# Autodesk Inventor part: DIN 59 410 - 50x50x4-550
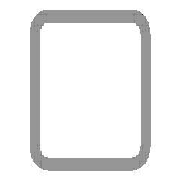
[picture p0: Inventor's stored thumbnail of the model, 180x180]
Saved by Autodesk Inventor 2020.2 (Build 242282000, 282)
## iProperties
Manager: www.cadconsulting.pl
Company: Fabian Stasiak CAD Consulting
Created: 2015-01
Part Number: DIN 59 410 - 50x50x4-550
Material: Stal, miękka
Description: Rurki stalowe o przekroju kwadratowym formowane na gorąco
Document SubType Name: Modellieren
Standard: DIN
Designer: F.Stasiak
Standards Organization: DIN
Language: pl-PL
Size Designation: 50x50x4
Categories: <MemberInstance><Categories><Category DisplayName="Kształtowniki konstrukcyjne" InternalName="089c4875-fa83-4c05-b084-43b9cc11f5ed" Mnemonic="GRDR"><CategoryPar
Stock Number: 50x50x4
Density: 7.85 g/cm^3
Appearance: Częściowo polerowana
Mass: 2999.78 g
Surface Area: 1924.59 cm^2
Volume: 382.138 cm^3
Catalog Web Link: www.expertbooks.pl
_CCFamilyMember: 40
_CCFamilyDisplayName: DIN 59410 (Kwadrat) - Rurki stalowe o przekroju kwadratowym formowane na gorąco
_FrameMemberDoc: Frame Member File
_Version: 15.0.0
_GetPNFromCC: 1
G_W: 50,000 mm
G_H: 50,000 mm
+8E38D49E-AF55-4C8E-92AA-B8B39F08F457+CUTDETAIL1: Wytnij
+63F55C9A-EFE3-425B-B887-7A3715F28EA0+CUTDETAIL2: Wytnij
G_L: 550,000 mm
IsCustomPart: 1
Author: F.Stasiak
Subject: Zbiór ćwiczeń. Autodesk Inventor 2020. Kurs Professional
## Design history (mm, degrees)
node "Płaszczyzna początkowa"
node "Płaszczyzna końcowa"
sketch "Szkic"
  geometry: L1 (-17, 25)-(17, 25); L2 (25, 17)-(25, -17); L3 (17, -25)-(-17, -25); L4 (-25, -17)-(-25, 17); L5 (-37.32, 0)-(37.32, 0) reference; L6 (0, -37.32)-(0, 37.32) reference; L7 (-17, 21)-(17, 21); L8 (21, 17)-(21, -17); L9 (17, -21)-(-17, -21); L10 (-21, -17)-(-21, 17); A1 r 8 centre (-17, 17) between (-17, 25) and (-25, 17); A2 r 8 centre (17, 17) between (25, 17) and (17, 25); A3 r 8 centre (17, -17) between (17, -25) and (25, -17); A4 r 8 centre (-17, -17) between (-25, -17) and (-17, -25); A5 r 4 centre (-17, 17) between (-17, 21) and (-21, 17); A6 r 4 centre (17, 17) between (21, 17) and (17, 21); A7 r 4 centre (17, -17) between (17, -21) and (21, -17); A8 r 4 centre (-17, -17) between (-21, -17) and (-17, -21); 3 further points
  constraints: 16 end point, 16 point on circle, 8 centre point, 8 tangent, 6 point on line, 4 parallel, 3 equal radius, 3 perpendicular, 1 horizontal, 7 other
  dimensions: "b" = 50 distance of point (-25, 25) point (25, 25); "msp_r" = 8 radius of A1 (= 2 x ParT); "d8" = 25 distance between parallel lines of L4 L6 (= d9); "d9" = 25 distance between parallel lines of L3 L5 (= 0.5 x b); "d10" = 4 distance between parallel lines of L3 L9 (= ParT)
extrude "Bryła" new body sketch "Szkic" taper "d4" = 0 deg; stored distance "NLG" = 10
node "Driven Length"
  sketch "Sketch2"
    geometry: L1 (0, 0)-(10, 0) reference
    constraints: 2 end point, 1 horizontal
  workplane "Work Plane3"
  sketch "Sketch3"
    geometry: L1 (-2, 25)-(12, 25) reference; L2 (-2, 575)-(12, 575) reference
    dimensions: "d14" = 550 distance between parallel lines of L1 L2 (derived)
node "Płaszczyzna konstrukcyjna4"
feature "Podział1"
node "Płaszczyzna konstrukcyjna5"
feature "Podział2"
body "Solid1"
other parameters: "ParT" = 4, "G_OFFSET_START" = -25 [user parameter; used in 1 equation term], "G_OFFSET_END" = -25 [user parameter; used in 1 equation term], "d11" = 25 (= -G_OFFSET_START), "d12" = 575 (= G_OFFSET_END + B_L), "G_L" = 550 (= d14) [user parameter], "d13" = 90 deg
